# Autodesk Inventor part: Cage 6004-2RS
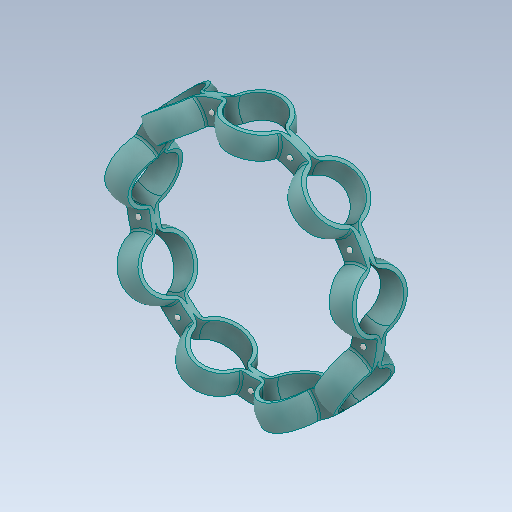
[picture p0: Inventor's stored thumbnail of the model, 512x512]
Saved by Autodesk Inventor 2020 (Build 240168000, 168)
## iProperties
Created: 2001-06
Part Number: Cage 6004-2RS
Material: Générique
Document SubType Name: Modeling
Designer: Bruno
Density: 1 g/cm^3
Appearance: Par défaut
Author: Bruno
Sending System: SolidWorks 2011
Last Author: frederic
Last Saved: 2012-02-20
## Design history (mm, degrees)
feature "Bossage-Symétrie1"
node "Solide1"
